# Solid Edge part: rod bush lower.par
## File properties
Author: Deepak Maini
Template: Normal.par
Last saved by: Robert a Rhodes jr
Revision: 2
Application: Solid Edge
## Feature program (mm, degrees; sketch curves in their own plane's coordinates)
sketch for "unnamed Protrusion 1" #1 plane through (0, 0, 0) normal (0, 0, 1) x-axis (1, 0, 0)
  circle centre (0, 0) radius 6
sketch for "unnamed Protrusion 1" #2 plane through (0, 0, 0) normal (0, 0, 1) x-axis (1, 0, 0)
  circle centre (0, 0) radius 7.5
extrude "unnamed Protrusion 1" add finite 24 along -normal
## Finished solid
Body 1: solid body, 4 faces, 4 edges, 0 vertices.
  Faces by surface: cylinder 2, plane 2
  Edges by curve: circle 4
Bounding box of the edges (mm): 15.000 x 15.000 x 24.000, from (-7.5, -7.5, -24) to (7.5, 7.5, 0).
Cylindrical faces by radius (mm): R6 x1, R7.5 x1
Planar faces by outward normal: +z 1, -z 1
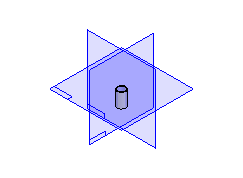
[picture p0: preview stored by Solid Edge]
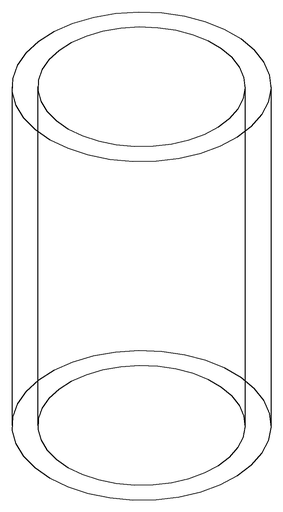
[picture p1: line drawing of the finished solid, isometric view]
